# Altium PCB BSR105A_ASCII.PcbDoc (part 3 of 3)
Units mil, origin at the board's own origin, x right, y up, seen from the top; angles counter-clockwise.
Board outline 4010.03 x 4016.63 mil, 6 copper layers (Top Layer, Mid-Layer 1, Mid-Layer 2, Mid-Layer 3, Mid-Layer 4, Bottom Layer), stack 61.2 mil thick; 167 components, 58 nets, 398 pads, 190 vias.
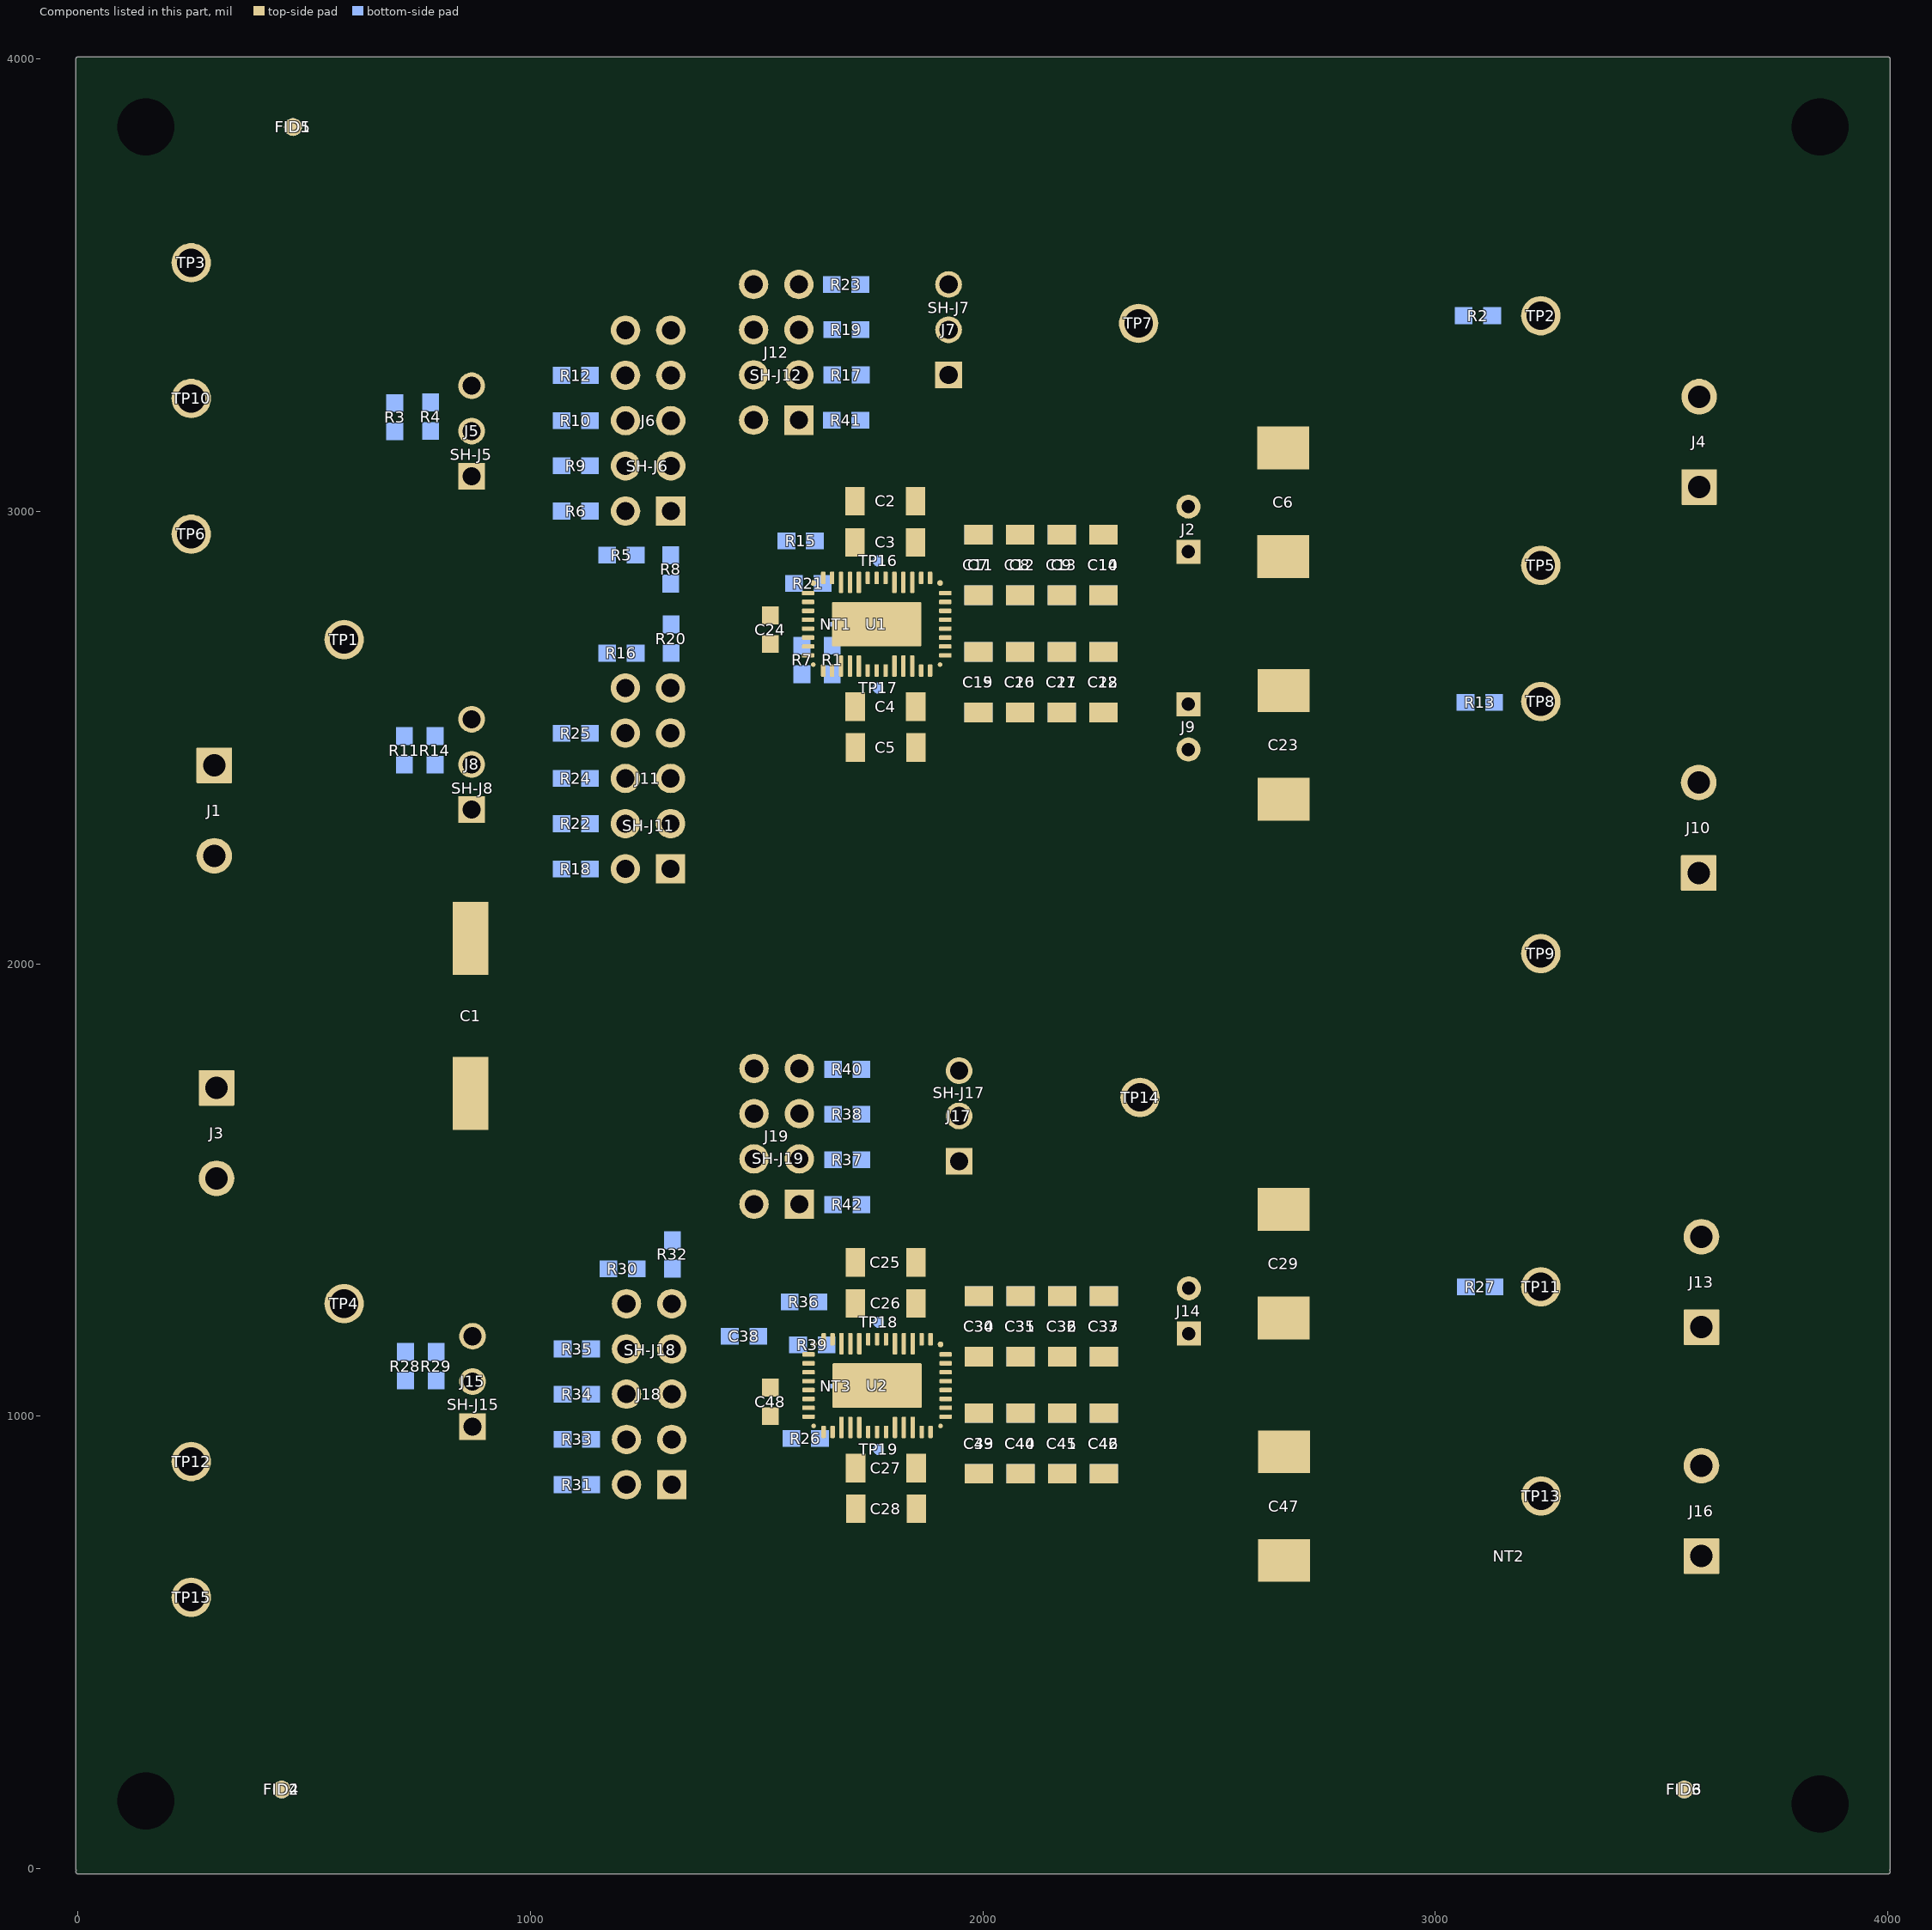
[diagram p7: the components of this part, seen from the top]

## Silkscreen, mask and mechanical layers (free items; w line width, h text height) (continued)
M17 Embedded Cavity:
  text ".Layer_Name" at 577,-858.49 h60
M18 Embedded Assembly:
  text ".Layer_Name" at 577,-858.49 h60
M19 Embedded Keepout:
  text ".Layer_Name" at 577,-858.49 h60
